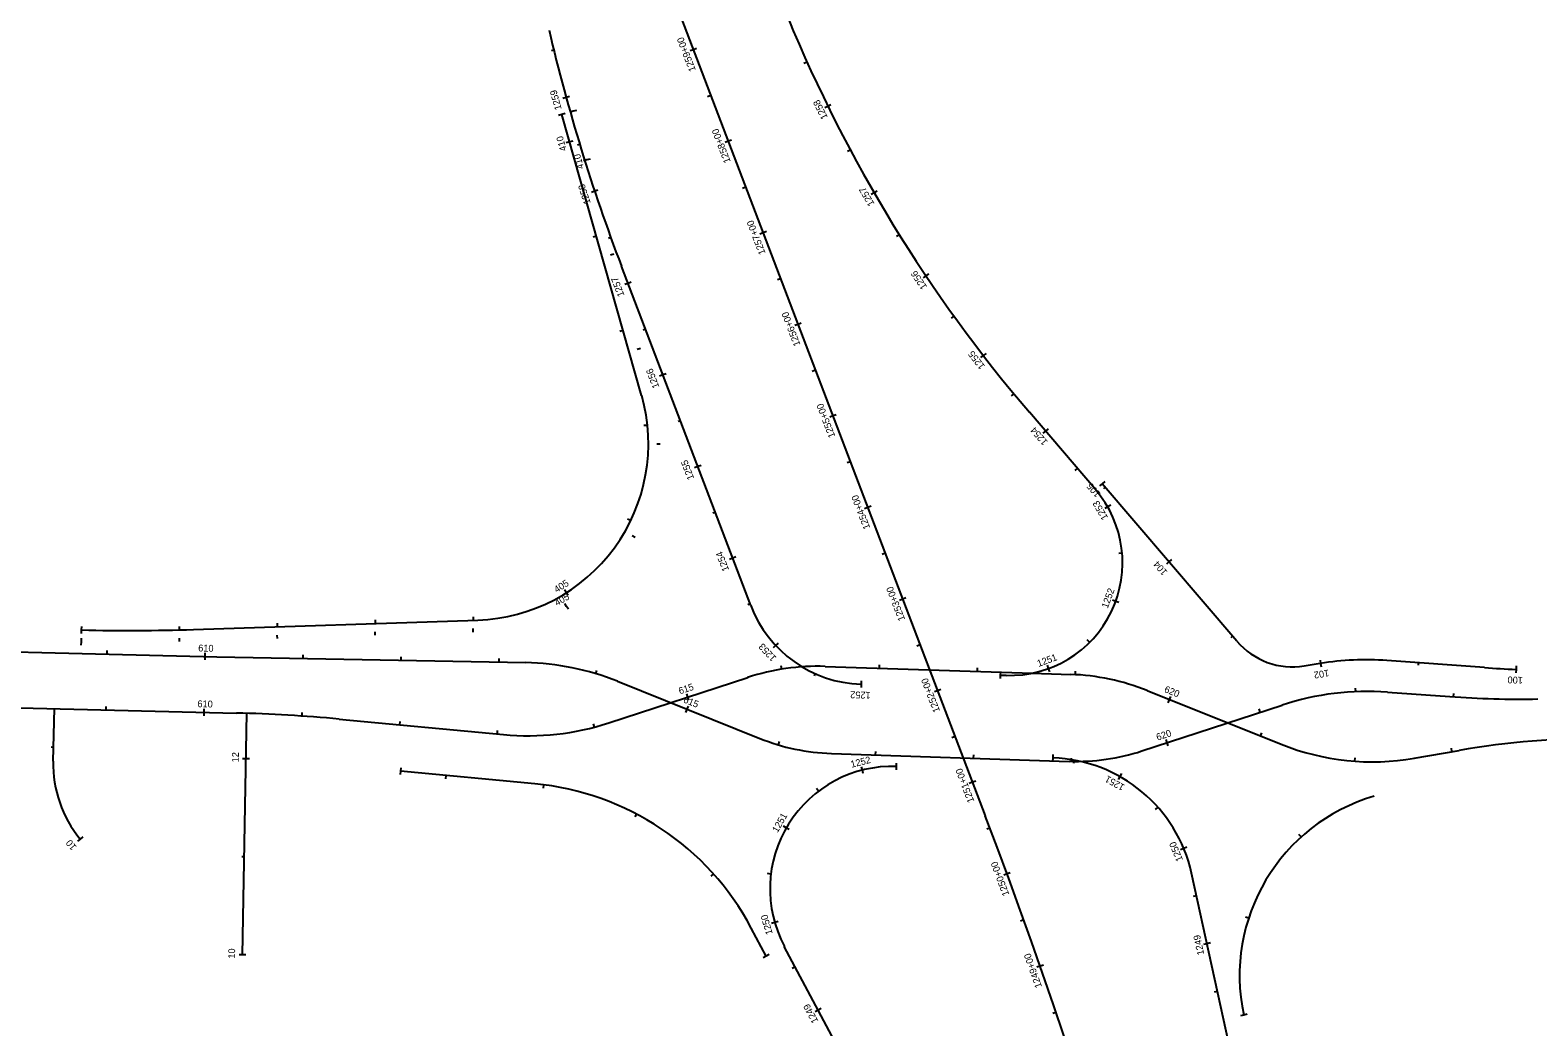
# Model space of a CAD drawing. Extents: x 596007 to 607538, y 326212 to 405053.
# Drawn here: x 602999 to 604538, y 349611 to 350629 of the extents above; entities that cross this region are included whole.
import ezdxf

# ---------------------------------------------------------------- set-up
doc = ezdxf.new("R2010")
doc.units = 0
for name, color, linetype in [('P_ALI', 7, 'Continuous'), ('P_ALI_200', 7, 'Continuous'), ('P_ALI_200_Sta', 7, 'Continuous'), ('P_ALI_200_Tic', 7, 'Continuous')]:
    doc.layers.add(name, color=color, linetype=linetype)

msp = doc.modelspace()

# ---------------------------------------------------------------- linework, layer by layer
at = {"layer": 'P_ALI'}
for points in [[(603623.4, 350255.6), (603541.9, 350542.5)], [(603734.7, 350041.4), (603602.8, 350387.7)], [(604086.5, 350159.8), (604019.2, 350238.5)], [(604230.7, 350005), (604093.3, 350165.6)], [(603166.2, 350016.9), (603456.2, 350026.5)], [(602805.1, 349998.4), (603189.8, 349989.1)], [(603189.8, 349989.1), (603504.9, 349983.1)], [(604315.9, 349982.3), (604299.5, 349979.6)], [(604483.5, 349978), (604383.8, 349985.1)], [(603589.8, 349921.5), (603731.6, 349967.9)], [(603810.6, 349979.2), (604011.8, 349972.6)], [(603989.7, 349970.3), (603995.3, 349970.1)], [(604011.8, 349972.6), (604061.2, 349970.9)], [(603598.7, 349964), (603743.9, 349905.7)], [(604139.2, 349954.5), (604275.8, 349899.7)], [(604384.5, 349953), (604447.9, 349948.4)], [(602670.3, 349944.6), (603210.1, 349931.6)], [(603023, 349882.4), (603024.3, 349936.1)], [(604133.8, 349892.9), (604277.1, 349939.8)], [(603216.1, 349684.8), (603220.7, 349931.3)], [(603314.9, 349925.4), (603482.5, 349909.6)], [(603817, 349890.3), (604059.8, 349882.3)], [(604411.8, 349885.5), (604457.5, 349893.5)], [(603514.4, 349859.4), (603377.4, 349872.3)], [(604246.7, 349484.4), (604184.5, 349768.1)], [(603750.5, 349683.6), (603735.3, 349712.1)], [(603879.4, 349486), (603769, 349693.4)]]:
    msp.add_lwpolyline(points, dxfattribs=at)
for centre, radius, start, end in [((605378.3, 351064.1), 1900, 193.2512, 200.8548), ((605159.2, 351213.4), 1500, 202.4065, 220.5362), ((603450.3, 350206.4), 180, 271.8911, 15.857), ((603999.1, 350085), 115, 268.1133, 40.5362), ((603851.5, 350085.9), 125, 200.8548, 268.1133), ((603100.2, 352015.8), 2000, 268.6212, 271.8911), ((604287.7, 350053.7), 75, 220.5362, 279.0172), ((603499.9, 349718.1), 265, 68.1133, 88.9058), ((604362.4, 349688.9), 297, 85.8706, 99.0172), ((603803.1, 349749.3), 230, 88.1133, 108.1133), ((604053.6, 349741.1), 230, 68.1473, 88.1133), ((604553.2, 350943.4), 968, 265.8706, 267.7776), ((604364.3, 349673.7), 280, 85.8706, 108.1473), ((604519.9, 350945.8), 1000, 265.8706, 271.0298), ((603174, 348432), 1500, 84.6117, 88.6212), ((603507.4, 350173.4), 265, 264.6117, 288.1133), ((603824.1, 350105.2), 215, 248.1133, 268.1133), ((604595, 349105.4), 800, 89.1186, 99.8942), ((604066.9, 350097.2), 215, 268.1133, 288.1473), ((604368.9, 350131.8), 250, 248.1473, 279.8942), ((603143, 349879.5), 120, 178.6212, 219.6028), ((603879.4, 349752.2), 125, 88.1133, 208.0179), ((604038, 349735.9), 150, 12.3818, 88.1133), ((603488.1, 349580.6), 280, 28.0179, 84.6117), ((604424.5, 349663.4), 191, 106.3142, 192.0769)]:
    msp.add_arc(centre, radius, start, end, dxfattribs=at)
at = {"layer": 'P_ALI_200'}
msp.add_lwpolyline([(603974.1, 349826.7), (602314.7, 354182.5)], dxfattribs=at)
msp.add_arc((598624.1, 347788.6), 5725, 359.0183, 20.8548, dxfattribs=at)
at = {"layer": 'P_ALI_200_Sta'}
for points in [[(603676.2, 350608.5), (603672.9, 350607.3)], [(603679.5, 350609.8), (603676.2, 350608.5)], [(603676.2, 350608.5), (603676.2, 350608.5)], [(603792.2, 350595.9), (603789, 350594.5)], [(603546.4, 350559.7), (603543.1, 350558.8)], [(603549.8, 350560.7), (603546.4, 350559.7)], [(603546.4, 350559.7), (603546.4, 350559.7)], [(603694, 350561.8), (603690.7, 350560.6)], [(603813.5, 350550.7), (603810.4, 350549.1)], [(603816.6, 350552.2), (603813.5, 350550.7)], [(603813.5, 350550.7), (603813.5, 350550.7)], [(603541.9, 350542.5), (603538.6, 350541.5)], [(603545.3, 350543.4), (603541.9, 350542.5)], [(603541.9, 350542.5), (603541.9, 350542.5)], [(603553.5, 350545.7), (603550.1, 350544.8)], [(603556.8, 350546.7), (603553.5, 350545.7)], [(603553.5, 350545.7), (603553.5, 350545.7)], [(603549.9, 350514.4), (603546.5, 350513.4)], [(603553.3, 350515.3), (603549.9, 350514.4)], [(603549.9, 350514.4), (603549.9, 350514.4)], [(603711.8, 350515.1), (603708.5, 350513.9)], [(603715.1, 350516.3), (603711.8, 350515.1)], [(603711.8, 350515.1), (603711.8, 350515.1)], [(603836.3, 350506.2), (603833.3, 350504.6)], [(603567.6, 350496.1), (603564.2, 350495.1)], [(603571, 350497), (603567.6, 350496.1)], [(603567.6, 350496.1), (603567.6, 350496.1)], [(603575.5, 350464.1), (603572.2, 350463)], [(603578.8, 350465.2), (603575.5, 350464.1)], [(603575.5, 350464.1), (603575.5, 350464.1)], [(603729.6, 350468.4), (603726.3, 350467.1)], [(603860.6, 350462.5), (603857.6, 350460.8)], [(603863.7, 350464.3), (603860.6, 350462.5)], [(603860.6, 350462.5), (603860.6, 350462.5)], [(603577.2, 350418.2), (603573.9, 350417.2)], [(603747.4, 350421.7), (603744.1, 350420.4)], [(603750.7, 350422.9), (603747.4, 350421.7)], [(603747.4, 350421.7), (603747.4, 350421.7)], [(603886.4, 350419.7), (603883.4, 350417.8)], [(603594.9, 350399.9), (603591.5, 350398.9)], [(603609.5, 350370), (603606.2, 350368.8)], [(603612.8, 350371.3), (603609.5, 350370)], [(603609.5, 350370), (603609.5, 350370)], [(603765.2, 350374.9), (603761.9, 350373.7)], [(603913.5, 350377.7), (603910.6, 350375.7)], [(603916.5, 350379.6), (603913.5, 350377.7)], [(603913.5, 350377.7), (603913.5, 350377.7)], [(603942.1, 350336.6), (603939.3, 350334.6)], [(603604.6, 350322), (603601.2, 350321)], [(603783, 350328.2), (603779.7, 350327)], [(603786.3, 350329.4), (603783, 350328.2)], [(603783, 350328.2), (603783, 350328.2)], [(603622.2, 350303.7), (603618.9, 350302.7)], [(603972, 350296.6), (603969.2, 350294.4)], [(603974.8, 350298.7), (603972, 350296.6)], [(603972, 350296.6), (603972, 350296.6)], [(603645.1, 350276.6), (603641.8, 350275.3)], [(603648.4, 350277.8), (603645.1, 350276.6)], [(603645.1, 350276.6), (603645.1, 350276.6)], [(603800.8, 350281.5), (603797.5, 350280.2)], [(604003.2, 350257.5), (604000.5, 350255.3)], [(603818.6, 350234.8), (603815.3, 350233.5)], [(603821.9, 350236), (603818.6, 350234.8)], [(603818.6, 350234.8), (603818.6, 350234.8)], [(603629.3, 350225.2), (603625.8, 350224.9)], [(604035.5, 350219.4), (604032.9, 350217.1)], [(604038.2, 350221.6), (604035.5, 350219.4)], [(604035.5, 350219.4), (604035.5, 350219.4)], [(603642.3, 350206.1), (603638.8, 350206.1)], [(603680.7, 350183.1), (603677.4, 350181.9)], [(603684, 350184.4), (603680.7, 350183.1)], [(603680.7, 350183.1), (603680.7, 350183.1)], [(603836.4, 350188), (603833.1, 350186.8)], [(604068, 350181.4), (604065.4, 350179.1)], [(604093.3, 350165.6), (604090.7, 350163.4)], [(604096, 350167.9), (604093.3, 350165.6)], [(604093.3, 350165.6), (604093.3, 350165.6)], [(603854.2, 350141.3), (603850.9, 350140.1)], [(603857.5, 350142.6), (603854.2, 350141.3)], [(603854.2, 350141.3), (603854.2, 350141.3)], [(604098.9, 350142.2), (604095.9, 350140.4)], [(604102, 350143.9), (604098.9, 350142.2)], [(604098.9, 350142.2), (604098.9, 350142.2)], [(603612.3, 350128), (603609.1, 350129.5)], [(603616.7, 350110.6), (603613.6, 350112.4)], [(603716.3, 350089.7), (603713, 350088.4)], [(603719.6, 350090.9), (603716.3, 350089.7)], [(603716.3, 350089.7), (603716.3, 350089.7)], [(603872, 350094.6), (603868.7, 350093.3)], [(604113.7, 350094.8), (604110.2, 350094.5)], [(604164.1, 350088.3), (604161.5, 350086)], [(604161.5, 350086), (604158.8, 350083.7)], [(604161.5, 350086), (604161.5, 350086)], [(603546.6, 350054.3), (603544.7, 350057.3)], [(603546.9, 350040.5), (603545.2, 350043.5)], [(603546.6, 350054.3), (603546.6, 350054.3)], [(603548.4, 350051.4), (603546.6, 350054.3)], [(603889.8, 350047.9), (603886.5, 350046.6)], [(603893.1, 350049.1), (603889.8, 350047.9)], [(603889.8, 350047.9), (603889.8, 350047.9)], [(604107.1, 350045.6), (604103.8, 350046.8)], [(604107.1, 350045.6), (604107.1, 350045.6)], [(604110.4, 350044.4), (604107.1, 350045.6)], [(603351.9, 350023.1), (603351.8, 350026.6)], [(603451.9, 350026.4), (603451.8, 350029.9)], [(603546.9, 350040.5), (603546.9, 350040.5)], [(603548.7, 350037.5), (603546.9, 350040.5)], [(603052, 350016.4), (603052.1, 350019.9)], [(603052, 350016.4), (603052, 350016.4)], [(603052, 350012.9), (603052, 350016.4)], [(603152, 350016.5), (603151.9, 350020)], [(603251.7, 350007.7), (603251.6, 350011.2)], [(603252, 350019.8), (603251.9, 350023.3)], [(603351.6, 350011), (603351.5, 350014.5)], [(603451.6, 350014.3), (603451.5, 350017.8)], [(603051.7, 350000.9), (603051.8, 350004.4)], [(603051.8, 350004.4), (603051.8, 350007.9)], [(603051.8, 350004.4), (603051.8, 350004.4)], [(603151.7, 350004.5), (603151.7, 350008)], [(603760.1, 350000.6), (603757.5, 349998.3)], [(603762.6, 350003), (603760.1, 350000.6)], [(603760.1, 350000.6), (603760.1, 350000.6)], [(603907.6, 350001.1), (603904.3, 349999.9)], [(604080.5, 350003.8), (604078, 350006.3)], [(603078, 349991.8), (603078.1, 349995.3)], [(603177.9, 349985.9), (603178, 349989.4)], [(603178, 349989.4), (603178, 349992.9)], [(603178, 349989.4), (603178, 349989.4)], [(603277.9, 349987.4), (603278, 349990.9)], [(603377.9, 349985.5), (603378, 349989)], [(603477.9, 349983.6), (603478, 349987.1)], [(603866.1, 349977.4), (603866.2, 349980.9)], [(604038.7, 349977.1), (604037.5, 349980.4)], [(604315.6, 349985.7), (604316.1, 349982.3)], [(604316.1, 349982.3), (604316.7, 349978.8)], [(604316.1, 349982.3), (604316.1, 349982.3)], [(603576.8, 349971.7), (603577.8, 349975.1)], [(603766.3, 349976.4), (603765.7, 349979.8)], [(603966, 349974.1), (603966.1, 349977.6)], [(603989.5, 349966.8), (603989.7, 349970.3)], [(603989.7, 349970.3), (603989.8, 349973.8)], [(603989.7, 349970.3), (603989.7, 349970.3)], [(604038.7, 349977.1), (604038.7, 349977.1)], [(604039.9, 349973.8), (604038.7, 349977.1)], [(604066, 349970.7), (604066.2, 349974.2)], [(604515.6, 349976.2), (604515.5, 349972.7)], [(604515.8, 349979.7), (604515.6, 349976.2)], [(604515.6, 349976.2), (604515.6, 349976.2)], [(603670.5, 349947.9), (603669.4, 349951.3)], [(603847.4, 349961), (603847.3, 349957.5)], [(603847.5, 349964.5), (603847.4, 349961)], [(603847.4, 349961), (603847.4, 349961)], [(603925.4, 349954.4), (603922.1, 349953.2)], [(603928.7, 349955.7), (603925.4, 349954.4)], [(603925.4, 349954.4), (603925.4, 349954.4)], [(604352, 349953.5), (604351.8, 349957)], [(604451.8, 349948.2), (604452, 349951.7)], [(603077.1, 349934.8), (603077.2, 349938.3)], [(603177.1, 349932.4), (603177.2, 349935.9)], [(603668.6, 349932.1), (603669.9, 349935.4)], [(603669.9, 349935.4), (603671.2, 349938.6)], [(603669.9, 349935.4), (603669.9, 349935.4)], [(603670.5, 349947.9), (603670.5, 349947.9)], [(603671.6, 349944.6), (603670.5, 349947.9)], [(604160.8, 349942.1), (604162.1, 349945.4)], [(604162.1, 349945.4), (604163.4, 349948.6)], [(604162.1, 349945.4), (604162.1, 349945.4)], [(604254.6, 349932.4), (604253.5, 349935.8)], [(603177, 349928.9), (603177.1, 349932.4)], [(603177.1, 349932.4), (603177.1, 349932.4)], [(603277, 349928.5), (603277.2, 349932)], [(603376.6, 349919.6), (603376.9, 349923.1)], [(603575.3, 349917.3), (603574.4, 349920.6)], [(603476.2, 349910.2), (603476.5, 349913.7)], [(603943.2, 349907.7), (603939.9, 349906.4)], [(604159.6, 349901.3), (604158.5, 349904.6)], [(604254.9, 349908.1), (604256.2, 349911.4)], [(603763, 349899), (603764, 349902.4)], [(603862.2, 349888.8), (603862.3, 349892.3)], [(603962.1, 349885.5), (603962.2, 349889)], [(604043, 349889.3), (604042.9, 349885.8)], [(604159.6, 349901.3), (604159.6, 349901.3)], [(604160.7, 349898), (604159.6, 349901.3)], [(604450.2, 349892.2), (604449.6, 349895.6)], [(603219.8, 349884.7), (603216.3, 349884.8)], [(603219.8, 349884.7), (603219.8, 349884.7)], [(603223.3, 349884.7), (603219.8, 349884.7)], [(603377.8, 349875.8), (603377.4, 349872.3)], [(603848.6, 349873.3), (603847.7, 349876.7)], [(603848.6, 349873.3), (603848.6, 349873.3)], [(603849.4, 349869.9), (603848.6, 349873.3)], [(603883.4, 349873.6), (603883.5, 349877.1)], [(603883.5, 349877.1), (603883.6, 349880.6)], [(603883.5, 349877.1), (603883.5, 349877.1)], [(604042.9, 349885.8), (604042.8, 349882.3)], [(604042.9, 349885.8), (604042.9, 349885.8)], [(604062.1, 349882.2), (604062.1, 349885.7)], [(604064.6, 349883.5), (604064, 349880.1)], [(604351, 349882.4), (604351.3, 349885.9)], [(603377.4, 349872.3), (603377.1, 349868.8)], [(603377.4, 349872.3), (603377.4, 349872.3)], [(603423.7, 349867.9), (603423.4, 349864.4)], [(603523.3, 349858.4), (603522.8, 349854.9)], [(603961, 349861), (603957.7, 349859.7)], [(603964.3, 349862.2), (603961, 349861)], [(603961, 349861), (603961, 349861)], [(604111.4, 349866.7), (604109.7, 349863.7)], [(604113.1, 349869.8), (604111.4, 349866.7)], [(604111.4, 349866.7), (604111.4, 349866.7)], [(603803.8, 349851.7), (603801.7, 349854.5)], [(603618.2, 349828.6), (603616.5, 349825.5)], [(604150.2, 349835.5), (604147.5, 349833.1)], [(603771, 349814.4), (603768, 349816.2)], [(603771, 349814.4), (603771, 349814.4)], [(603774, 349812.7), (603771, 349814.4)], [(603978.8, 349814.2), (603975.5, 349813)], [(603050.5, 349803), (603047.8, 349800.7)], [(603053.2, 349805.2), (603050.5, 349803)], [(603050.5, 349803), (603050.5, 349803)], [(604296.5, 349805.2), (604294.1, 349807.8)], [(604176.6, 349793.3), (604173.3, 349791.9)], [(604179.8, 349794.6), (604176.6, 349793.3)], [(604176.6, 349793.3), (604176.6, 349793.3)], [(603696.7, 349767.5), (603694, 349765.1)], [(603755.3, 349767.3), (603751.8, 349767.7)], [(603996.3, 349767.4), (603993, 349766.2)], [(603999.6, 349768.6), (603996.3, 349767.4)], [(603996.3, 349767.4), (603996.3, 349767.4)], [(604189.5, 349745.1), (604186.1, 349744.3)], [(603762.6, 349718.8), (603759.2, 349717.8)], [(604013.4, 349720.4), (604010.1, 349719.2)], [(604242.8, 349722.2), (604239.4, 349723.2)], [(603759.2, 349717.8), (603755.8, 349716.8)], [(603759.2, 349717.8), (603759.2, 349717.8)], [(604200.2, 349696.2), (604196.8, 349695.5)], [(604203.7, 349697), (604200.2, 349696.2)], [(604200.2, 349696.2), (604200.2, 349696.2)], [(603216.1, 349684.8), (603212.6, 349684.8)], [(603216.1, 349684.8), (603216.1, 349684.8)], [(603219.6, 349684.7), (603216.1, 349684.8)], [(603750.5, 349683.6), (603747.4, 349681.9)], [(603753.6, 349685.2), (603750.5, 349683.6)], [(603750.5, 349683.6), (603750.5, 349683.6)], [(604030, 349673.3), (604026.7, 349672.1)], [(604033.3, 349674.4), (604030, 349673.3)], [(604030, 349673.3), (604030, 349673.3)], [(603780.2, 349672.5), (603777.1, 349670.9)], [(604211, 349647.4), (604207.5, 349646.6)], [(603803.7, 349628.4), (603800.6, 349626.7)], [(603806.7, 349630), (603803.7, 349628.4)], [(603803.7, 349628.4), (603803.7, 349628.4)], [(604046.3, 349626), (604043, 349624.8)], [(604237.7, 349623.4), (604234.3, 349622.7)], [(604241.1, 349624.2), (604237.7, 349623.4)], [(604237.7, 349623.4), (604237.7, 349623.4)]]:
    msp.add_lwpolyline(points, dxfattribs=at)
at = {"layer": 'P_ALI_200_Tic'}
for points in [[(603533.8, 350608.1), (603531.4, 350607.5)], [(603560.4, 350511.7), (603558, 350511)], [(603591.9, 350416.9), (603589.6, 350416)], [(603627.3, 350323.3), (603625, 350322.4)], [(603662.9, 350229.9), (603660.6, 350229)], [(604096.5, 350162), (604094.6, 350160.4)], [(603698.5, 350136.4), (603696.2, 350135.5)], [(603734.1, 350043), (603731.8, 350042.1)], [(604226.4, 350010), (604224.6, 350008.4)], [(604415.8, 349982.8), (604415.7, 349980.3)], [(603800.5, 349971.8), (603799.5, 349969.5)], [(603023.4, 349896.5), (603020.9, 349896.6)], [(603218, 349784.7), (603215.5, 349784.8)]]:
    msp.add_lwpolyline(points, dxfattribs=at)

# ---------------------------------------------------------------- texts
at = {"layer": 'P_ALI_200_Sta'}
for s, height, rotation, p in [('1259+00', 7, 110.8548, (603678.8, 350587.8)), ('1259', 7, 105.3925, (603541.9, 350548.1)), ('1258', 7, 116.2185, (603813.5, 350539.5)), ('410', 0.0000000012, 105.857, (603537.1, 350541.1)), ('410', 0.0000000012, 105.857, (603548.7, 350544.4)), ('410', 7, 105.857, (603547.1, 350506.1)), ('1258+00', 7, 110.8548, (603714.4, 350494.4)), ('410', 7, 105.857, (603564.7, 350487.8)), ('1258', 7, 108.408, (603571.6, 350452.2)), ('1257', 7, 120.0383, (603861.3, 350451.3)), ('1257+00', 7, 110.8548, (603750, 350400.9)), ('1256', 7, 123.858, (603915, 350366.6)), ('1257', 7, 110.8548, (603606, 350358)), ('1256+00', 7, 110.8548, (603785.6, 350307.5)), ('1255', 7, 127.6777, (603974.2, 350285.6)), ('1256', 7, 110.8548, (603641.6, 350264.5)), ('1255+00', 7, 110.8548, (603821.2, 350214)), ('1254', 7, 130.5362, (604038.3, 350208.5)), ('1255', 7, 110.8548, (603677.2, 350171.1)), ('105', 7, 130.5362, (604092.3, 350155.4)), ('1254+00', 7, 110.8548, (603856.8, 350120.6)), ('1253', 7, 119.7778, (604099.6, 350131)), ('1254', 7, 110.8548, (603712.8, 350077.7)), ('104', 7, 130.5362, (604160.4, 350075.7)), ('405', 7, 32.339, (603536.7, 350054)), ('1253+00', 7, 110.8548, (603892.4, 350027.1)), ('1252', 7, 69.9554, (604099, 350037.9)), ('405', 7, 30.2317, (603537, 350040.5)), ('400', 0.0000000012, 358.6212, (603052.2, 350021.4)), ('400', 0.0000000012, 358.6212, (603051.9, 350009.4)), ('610', 7, 358.6212, (603170.9, 349994.5)), ('1253', 7, 133.0052, (603761.4, 349988.2)), ('1251', 7, 20.133, (604028.4, 349978.6)), ('1252+00', 7, 110.8548, (603928, 349933.7)), ('1250', 0.0000000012, 358.1133, (603989.8, 349975.3)), ('102', 7, 188.9667, (604324.3, 349976)), ('100', 7, 177.7776, (604522.7, 349968.4)), ('615', 7, 18.1133, (603662.4, 349950.6)), ('1252', 7, 178.1133, (603857.2, 349953.1)), ('620', 7, 338.1473, (604156, 349953.2)), ('610', 7, 358.6212, (603170.1, 349937.6)), ('615', 7, 338.1133, (603665.4, 349942.6)), ('620', 7, 18.1473, (604149.8, 349903.4)), ('12', 7, 88.9261, (603212.3, 349881.2)), ('1252', 7, 14.2823, (603837.6, 349875.7)), ('1252', 0.0000000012, 358.1133, (603883.7, 349882.1)), ('1251+00', 7, 110.8548, (603963, 349841.6)), ('1251', 0.0000000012, 178.1133, (604042.7, 349880.8)), ('304', 0.0000000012, 174.6117, (603377, 349867.3)), ('1251', 7, 150.6763, (604116.9, 349857.9)), ('1251', 7, 60.1189, (603762.1, 349809)), ('10', 7, 129.6028, (603047.3, 349795.1)), ('1250', 7, 112.4791, (604175.9, 349781.8)), ('1250+00', 7, 110.2213, (603998.7, 349746.4)), ('1250', 7, 105.9555, (603757.2, 349706.5)), ('1249', 7, 102.3818, (604197.5, 349685.4)), ('10', 7, 88.9261, (603208.5, 349680.9)), ('300', 0.0000000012, 118.0179, (603746.1, 349681.2)), ('1249+00', 7, 109.2205, (604032, 349652.4)), ('1249', 7, 118.0179, (603803.9, 349617.2)), ('200', 0.0000000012, 102.0769, (604232.8, 349622.4))]:
    msp.add_text(s, height=height, rotation=rotation, dxfattribs=at).set_placement(p)

doc.saveas('drawing.dxf')
